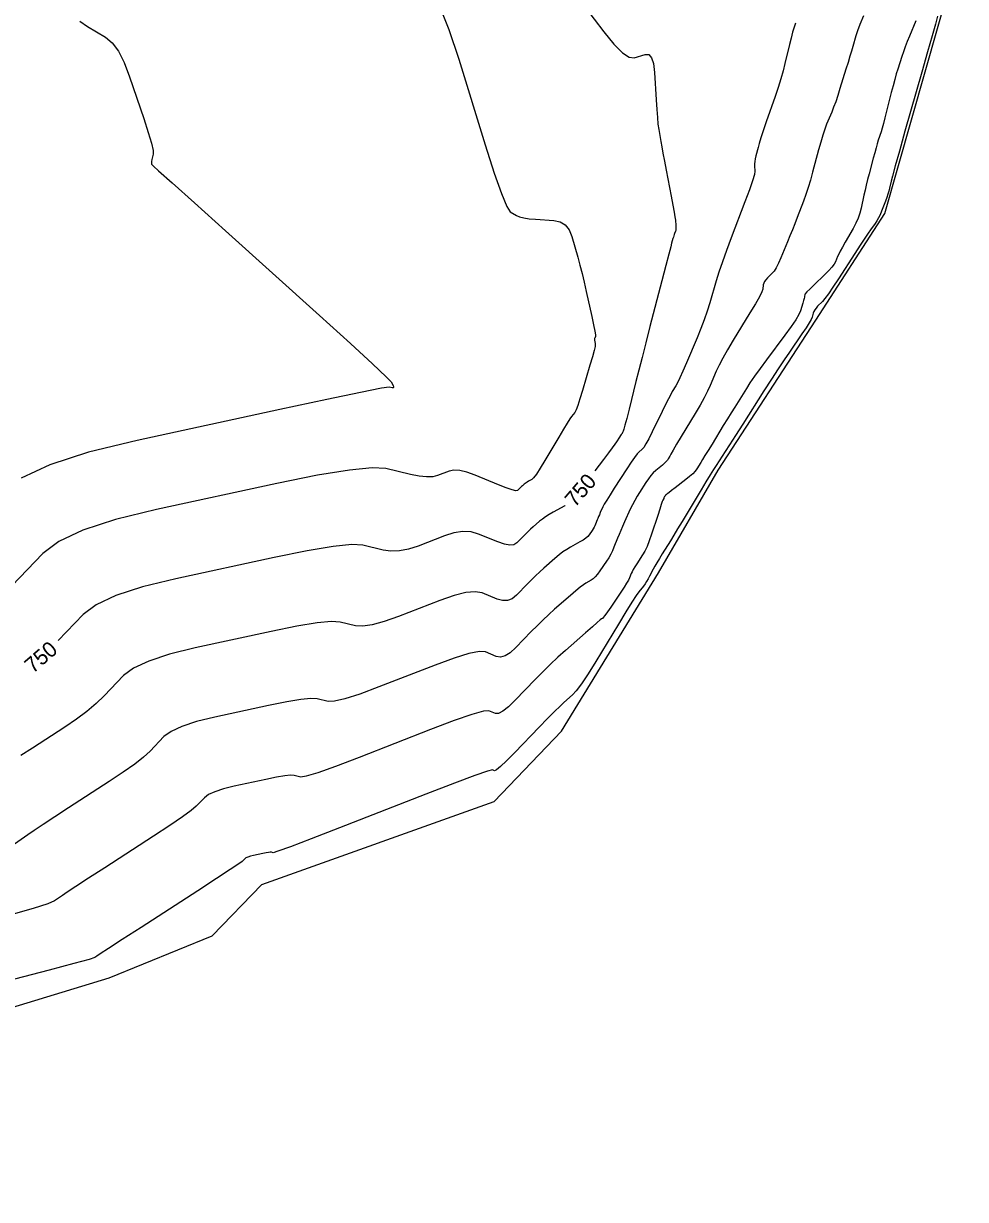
# Model space of a CAD drawing. Extents: x 2079879 to 2092887, y 778083 to 784051.
# Drawn here: x 2084480.9 to 2084652.5, y 780446.5 to 780660.6 of the extents above; entities that cross this region are included whole.
import ezdxf

# ---------------------------------------------------------------- set-up
doc = ezdxf.new("R2010")
doc.units = 0
for name, color, linetype in [('DT_X_Contour_Major', 7, 'Continuous'), ('DT_X_Contour_Minor', 7, 'Continuous'), ('DT_X_TIN_Hull', 7, 'Continuous')]:
    doc.layers.add(name, color=color, linetype=linetype)

msp = doc.modelspace()

# ---------------------------------------------------------------- linework, layer by layer
at = {"layer": 'DT_X_Contour_Major'}
for points in [[(2084581.34, 780666.04), (2084586.65, 780659.08), (2084588.48, 780656.82), (2084590.01, 780655.28), (2084591.23, 780654.45), (2084592.14, 780654.33), (2084594.15, 780654.96), (2084594.82, 780654.93), (2084595.33, 780654.38), (2084595.68, 780653.3), (2084595.87, 780651.69), (2084596.15, 780646.71), (2084596.26, 780644.97), (2084596.38, 780643.49), (2084596.5, 780642.28), (2084596.64, 780641.32), (2084597.01, 780639.12), (2084597.17, 780638.17), (2084597.39, 780636.99), (2084597.66, 780635.56), (2084597.98, 780633.9), (2084598.91, 780629.14), (2084599.21, 780627.53), (2084599.44, 780626.27), (2084599.59, 780625.37), (2084599.66, 780624.82), (2084599.74, 780623.81), (2084599.76, 780623.47), (2084599.75, 780623.17), (2084599.73, 780622.94), (2084599.68, 780622.76), (2084599.52, 780622.35), (2084599.46, 780622.17), (2084599.39, 780621.96), (2084599.31, 780621.72), (2084599.22, 780621.43), (2084598.98, 780620.61), (2084598.81, 780619.96), (2084598.45, 780618.59), (2084597.91, 780616.53), (2084597.19, 780613.76), (2084595.04, 780605.44), (2084594.27, 780602.47), (2084593.59, 780599.81), (2084592.99, 780597.45), (2084592.48, 780595.41), (2084591.22, 780590.36), (2084590.8, 780588.69), (2084590.48, 780587.47), (2084590.28, 780586.71), (2084590.18, 780586.39), (2084590.06, 780586.14), (2084590.02, 780586.06), (2084589.98, 780586), (2084589.96, 780585.96), (2084589.95, 780585.94), (2084589.93, 780585.92), (2084589.9, 780585.88), (2084589.81, 780585.75), (2084589.68, 780585.56), (2084589.5, 780585.28), (2084588.95, 780584.44), (2084588.65, 780584), (2084588.16, 780583.32), (2084587.47, 780582.4), (2084586.59, 780581.24), (2084584.99, 780579.12)], [(2084579.58, 780572.82), (2084579.52, 780572.79), (2084577.41, 780571.63), (2084576.66, 780571.2), (2084576, 780570.78), (2084575.43, 780570.37), (2084574.94, 780569.97), (2084573.75, 780568.93), (2084573.3, 780568.53), (2084572.86, 780568.12), (2084572.42, 780567.69), (2084571.98, 780567.24), (2084570.81, 780566.03), (2084570.26, 780565.7), (2084569.49, 780565.61), (2084568.51, 780565.78), (2084567.31, 780566.2), (2084563.82, 780567.64), (2084562.45, 780568.03), (2084560.95, 780568.11), (2084559.33, 780567.87), (2084557.59, 780567.33), (2084552.78, 780565.46), (2084551.03, 780564.88), (2084549.38, 780564.57), (2084547.85, 780564.51), (2084546.42, 780564.72), (2084542.75, 780565.6), (2084540.7, 780565.71), (2084537.33, 780565.37), (2084532.61, 780564.59), (2084526.57, 780563.36), (2084508.67, 780559.5), (2084502.58, 780558), (2084497.73, 780556.42), (2084494.13, 780554.75), (2084491.78, 780553), (2084487.23, 780548.25)]]:
    msp.add_lwpolyline(points, dxfattribs=at)
at = {"layer": 'DT_X_Contour_Minor'}
for points in [[(2084556.57, 780664.07), (2084558.41, 780659.5), (2084560.22, 780654.08), (2084565.04, 780638.52), (2084566.67, 780633.38), (2084567.97, 780629.63), (2084568.93, 780627.28), (2084569.54, 780626.33), (2084570.74, 780625.63), (2084571.29, 780625.39), (2084572.04, 780625.2), (2084573, 780625.06), (2084574.16, 780624.96), (2084577.52, 780624.75), (2084578.68, 780624.51), (2084579.61, 780623.94), (2084580.33, 780623.03), (2084580.83, 780621.8), (2084581.88, 780618.06), (2084582.27, 780616.62), (2084582.66, 780615.1), (2084583.04, 780613.51), (2084583.43, 780611.83), (2084584.44, 780607.24), (2084584.77, 780605.73), (2084584.99, 780604.61), (2084585.1, 780603.91), (2084585.11, 780603.6), (2084585, 780603.33), (2084584.96, 780603.22), (2084584.95, 780603.08), (2084584.95, 780602.91), (2084584.98, 780602.73), (2084585.06, 780602.19), (2084585.03, 780601.8), (2084584.86, 780601.04), (2084584.56, 780599.89), (2084584.11, 780598.36), (2084582.76, 780593.78), (2084582.29, 780592.24), (2084581.89, 780591.06), (2084581.57, 780590.24), (2084581.32, 780589.78), (2084580.75, 780589.03), (2084580.44, 780588.59), (2084579.95, 780587.81), (2084579.28, 780586.71), (2084578.42, 780585.28), (2084575.88, 780581.03), (2084575.02, 780579.62), (2084574.34, 780578.57), (2084573.84, 780577.9), (2084573.51, 780577.58), (2084572.88, 780577.24), (2084572.66, 780577.11), (2084572.46, 780576.98), (2084572.29, 780576.86), (2084572.14, 780576.74), (2084571.79, 780576.43), (2084571.65, 780576.31), (2084571.52, 780576.19), (2084571.39, 780576.06), (2084571.26, 780575.93), (2084570.91, 780575.56), (2084570.59, 780575.53), (2084569.91, 780575.69), (2084568.86, 780576.05), (2084567.45, 780576.61), (2084563.19, 780578.38), (2084561.69, 780578.92), (2084560.4, 780579.22), (2084559.31, 780579.28), (2084558.43, 780579.09), (2084556.35, 780578.29), (2084555.46, 780578.07), (2084554.34, 780578.03), (2084552.99, 780578.17), (2084551.42, 780578.49), (2084546.92, 780579.57), (2084544.41, 780579.71), (2084540.27, 780579.29), (2084534.49, 780578.33), (2084527.08, 780576.83), (2084505.13, 780572.09), (2084497.66, 780570.26), (2084491.72, 780568.32), (2084487.31, 780566.27), (2084484.43, 780564.12), (2084478.77, 780558.23)], [(2084643.5, 780661.07), (2084642.33, 780658.32), (2084641.91, 780657.32), (2084641.54, 780656.35), (2084641.21, 780655.44), (2084640.91, 780654.57), (2084640.19, 780652.31), (2084639.91, 780651.41), (2084639.62, 780650.4), (2084639.32, 780649.28), (2084639.01, 780648.06), (2084638.15, 780644.63), (2084637.84, 780643.44), (2084637.57, 780642.42), (2084637.34, 780641.57), (2084637.14, 780640.9), (2084636.64, 780639.35), (2084636.45, 780638.71), (2084636.23, 780637.94), (2084635.98, 780637.06), (2084635.71, 780636.06), (2084634.96, 780633.23), (2084634.69, 780632.19), (2084634.45, 780631.19), (2084634.22, 780630.24), (2084634.02, 780629.33), (2084633.52, 780626.96), (2084633.28, 780626.06), (2084632.96, 780625.15), (2084632.55, 780624.23), (2084632.05, 780623.29), (2084630.61, 780620.77), (2084630.12, 780619.9), (2084629.72, 780619.17), (2084629.42, 780618.59), (2084629.22, 780618.15), (2084628.82, 780617.18), (2084628.59, 780616.77), (2084628.2, 780616.26), (2084627.65, 780615.65), (2084626.94, 780614.94), (2084624.83, 780612.91), (2084624.14, 780612.24), (2084623.64, 780611.73), (2084623.34, 780611.38), (2084623.23, 780611.2), (2084623.2, 780610.94), (2084623.17, 780610.79), (2084623.11, 780610.53), (2084623.01, 780610.17), (2084622.87, 780609.7), (2084622.46, 780608.3), (2084622.17, 780607.63), (2084621.6, 780606.66), (2084620.75, 780605.41), (2084619.63, 780603.87), (2084616.26, 780599.36), (2084615.09, 780597.77), (2084614.09, 780596.37), (2084613.26, 780595.16), (2084612.6, 780594.15), (2084611.08, 780591.72), (2084610.48, 780590.76), (2084609.83, 780589.72), (2084609.14, 780588.59), (2084608.39, 780587.38), (2084606.34, 780584.03), (2084605.63, 780582.88), (2084605.05, 780581.93), (2084604.6, 780581.2), (2084604.28, 780580.67), (2084603.59, 780579.54), (2084603.27, 780579.1), (2084602.83, 780578.62), (2084602.27, 780578.11), (2084601.59, 780577.56), (2084599.6, 780576.04), (2084598.95, 780575.54), (2084598.47, 780575.17), (2084598.16, 780574.94), (2084598.04, 780574.84), (2084597.93, 780574.75), (2084597.89, 780574.71), (2084597.86, 780574.67), (2084597.82, 780574.63), (2084597.79, 780574.58), (2084597.71, 780574.46), (2084597.67, 780574.4), (2084597.63, 780574.33), (2084597.59, 780574.23), (2084597.54, 780574.12), (2084597.39, 780573.81), (2084597.29, 780573.54), (2084597.1, 780572.99), (2084596.82, 780572.14), (2084596.45, 780571.01), (2084595.33, 780567.59), (2084594.91, 780566.39), (2084594.5, 780565.37), (2084594.1, 780564.51), (2084593.7, 780563.83), (2084592.64, 780562.24), (2084592.28, 780561.68), (2084591.99, 780561.19), (2084591.77, 780560.78), (2084591.61, 780560.45), (2084591.3, 780559.66), (2084591.11, 780559.27), (2084590.79, 780558.71), (2084590.31, 780557.97), (2084589.7, 780557.05), (2084587.88, 780554.35), (2084587.28, 780553.46), (2084586.83, 780552.82), (2084586.53, 780552.42), (2084586.39, 780552.26), (2084586.22, 780552.17), (2084585.99, 780551.99), (2084585.43, 780551.51), (2084584.54, 780550.74), (2084583.32, 780549.67), (2084579.63, 780546.43), (2084578.25, 780545.19), (2084576.87, 780543.9), (2084575.5, 780542.57), (2084574.14, 780541.18), (2084570.5, 780537.41), (2084569.25, 780536.2), (2084568.23, 780535.39), (2084567.44, 780534.97), (2084566.89, 780534.96), (2084565.7, 780535.45), (2084564.7, 780535.37), (2084562.6, 780534.78), (2084559.38, 780533.66), (2084555.06, 780532.02), (2084542.05, 780526.97), (2084537.73, 780525.32), (2084534.51, 780524.18), (2084532.4, 780523.53), (2084531.41, 780523.39), (2084530.23, 780523.67), (2084529.57, 780523.71), (2084528.49, 780523.6), (2084526.97, 780523.35), (2084525.03, 780522.96), (2084519.27, 780521.71), (2084517.32, 780521.23), (2084515.76, 780520.72), (2084514.6, 780520.19), (2084513.85, 780519.62), (2084512.37, 780518.08), (2084511.46, 780517.3), (2084509.87, 780516.14), (2084507.58, 780514.57), (2084504.59, 780512.62), (2084495.71, 780506.88), (2084492.73, 780504.95), (2084490.45, 780503.47), (2084488.87, 780502.43), (2084487.99, 780501.83), (2084486.56, 780500.84), (2084485.32, 780500.31), (2084482.66, 780499.47), (2084478.58, 780498.32)], [(2084633.94, 780661.97), (2084633.29, 780660.45), (2084632.83, 780659.24), (2084632.53, 780658.35), (2084631.98, 780656.39), (2084631.75, 780655.58), (2084631.47, 780654.63), (2084631.14, 780653.53), (2084630.75, 780652.28), (2084629.65, 780648.76), (2084629.25, 780647.5), (2084628.87, 780646.37), (2084628.5, 780645.36), (2084628.15, 780644.47), (2084627.23, 780642.27), (2084626.88, 780641.36), (2084626.52, 780640.28), (2084626.14, 780639.02), (2084625.74, 780637.59), (2084624.67, 780633.56), (2084624.27, 780632.09), (2084623.85, 780630.72), (2084623.43, 780629.45), (2084623.01, 780628.27), (2084621.85, 780625.27), (2084621.42, 780624.14), (2084620.98, 780623.03), (2084620.54, 780621.93), (2084620.09, 780620.83), (2084618.88, 780617.93), (2084618.44, 780616.94), (2084618.04, 780616.14), (2084617.66, 780615.53), (2084617.31, 780615.12), (2084616.43, 780614.27), (2084616.13, 780613.95), (2084615.91, 780613.64), (2084615.77, 780613.33), (2084615.69, 780613.02), (2084615.6, 780612.22), (2084615.43, 780611.72), (2084614.98, 780610.83), (2084614.25, 780609.56), (2084613.25, 780607.89), (2084610.22, 780602.93), (2084609.17, 780601.19), (2084608.31, 780599.66), (2084607.62, 780598.36), (2084607.12, 780597.27), (2084606.02, 780594.69), (2084605.54, 780593.64), (2084604.92, 780592.44), (2084604.17, 780591.09), (2084603.28, 780589.59), (2084600.73, 780585.38), (2084599.88, 780583.98), (2084599.25, 780582.92), (2084598.83, 780582.21), (2084598.63, 780581.84), (2084598.38, 780581.33), (2084598.24, 780581.12), (2084598.01, 780580.85), (2084597.7, 780580.55), (2084597.3, 780580.19), (2084596.1, 780579.18), (2084595.65, 780578.76), (2084595.21, 780578.27), (2084594.76, 780577.7), (2084594.31, 780577.05), (2084593.12, 780575.22), (2084592.68, 780574.52), (2084592.26, 780573.77), (2084591.85, 780572.98), (2084591.45, 780572.14), (2084590.41, 780569.86), (2084590.04, 780569.03), (2084589.7, 780568.26), (2084589.4, 780567.55), (2084589.14, 780566.9), (2084588.48, 780565.22), (2084588.2, 780564.59), (2084587.88, 780563.96), (2084587.52, 780563.31), (2084587.1, 780562.67), (2084585.92, 780560.93), (2084585.49, 780560.33), (2084585.08, 780559.85), (2084584.7, 780559.48), (2084584.33, 780559.23), (2084583.38, 780558.71), (2084582.94, 780558.42), (2084582.31, 780557.95), (2084581.51, 780557.29), (2084580.53, 780556.44), (2084577.67, 780553.93), (2084576.6, 780552.97), (2084575.53, 780551.98), (2084574.47, 780550.94), (2084573.42, 780549.87), (2084570.6, 780546.95), (2084569.59, 780546.03), (2084568.65, 780545.46), (2084567.8, 780545.24), (2084567.03, 780545.37), (2084565.07, 780546.18), (2084563.95, 780546.26), (2084562.05, 780545.89), (2084559.36, 780545.06), (2084555.9, 780543.79), (2084545.63, 780539.8), (2084542.16, 780538.51), (2084539.47, 780537.64), (2084537.55, 780537.19), (2084536.41, 780537.17), (2084534.4, 780537.65), (2084533.28, 780537.71), (2084531.43, 780537.52), (2084528.85, 780537.1), (2084525.54, 780536.42), (2084515.74, 780534.31), (2084512.4, 780533.49), (2084509.75, 780532.62), (2084507.78, 780531.71), (2084506.49, 780530.75), (2084503.97, 780528.12), (2084502.79, 780527.03), (2084501.16, 780525.74), (2084499.07, 780524.25), (2084496.52, 780522.56), (2084489.12, 780517.77), (2084486.58, 780516.12), (2084484.49, 780514.76), (2084482.87, 780513.68), (2084481.71, 780512.89), (2084479.24, 780511.17)], [(2084647.41, 780661.91), (2084647.03, 780660.51), (2084646.43, 780658.34), (2084645.61, 780655.43), (2084644.57, 780651.76), (2084641.5, 780640.97), (2084640.48, 780637.37), (2084639.72, 780634.66), (2084639.22, 780632.83), (2084638.98, 780631.9), (2084638.69, 780630.59), (2084638.57, 780630.08), (2084638.4, 780629.52), (2084638.19, 780628.91), (2084637.94, 780628.25), (2084637.23, 780626.44), (2084636.95, 780625.79), (2084636.67, 780625.2), (2084636.37, 780624.67), (2084636.05, 780624.2), (2084635.2, 780623.03), (2084634.79, 780622.43), (2084634.17, 780621.51), (2084633.35, 780620.27), (2084632.34, 780618.71), (2084629.38, 780614.12), (2084628.36, 780612.57), (2084627.54, 780611.37), (2084626.92, 780610.52), (2084626.49, 780610.01), (2084625.59, 780609.12), (2084625.29, 780608.79), (2084625.05, 780608.47), (2084624.88, 780608.17), (2084624.77, 780607.88), (2084624.57, 780607.12), (2084624.4, 780606.72), (2084624.03, 780606.07), (2084623.47, 780605.19), (2084622.71, 780604.07), (2084620.43, 780600.76), (2084619.5, 780599.38), (2084618.42, 780597.75), (2084617.19, 780595.86), (2084615.81, 780593.72), (2084611.93, 780587.64), (2084610.6, 780585.57), (2084609.53, 780583.91), (2084608.73, 780582.66), (2084608.19, 780581.82), (2084607.09, 780580.14), (2084606.61, 780579.39), (2084605.99, 780578.4), (2084605.24, 780577.16), (2084604.34, 780575.68), (2084601.79, 780571.42), (2084600.88, 780569.91), (2084600.07, 780568.57), (2084599.36, 780567.41), (2084598.76, 780566.42), (2084597.27, 780564.01), (2084596.76, 780563.16), (2084596.31, 780562.41), (2084595.94, 780561.77), (2084595.65, 780561.23), (2084594.97, 780559.94), (2084594.71, 780559.46), (2084594.43, 780559.01), (2084594.14, 780558.58), (2084593.83, 780558.17), (2084592.99, 780557.11), (2084592.52, 780556.44), (2084591.75, 780555.24), (2084590.67, 780553.5), (2084589.28, 780551.23), (2084585.17, 780544.45), (2084583.75, 780542.16), (2084582.57, 780540.38), (2084581.62, 780539.11), (2084580.92, 780538.34), (2084579.36, 780536.98), (2084578.65, 780536.31), (2084577.65, 780535.35), (2084576.39, 780534.07), (2084574.86, 780532.49), (2084570.4, 780527.88), (2084568.92, 780526.37), (2084567.81, 780525.31), (2084567.09, 780524.7), (2084566.74, 780524.54), (2084566.33, 780524.71), (2084565.46, 780524.48), (2084563.15, 780523.66), (2084559.4, 780522.26), (2084554.21, 780520.26), (2084538.47, 780514.14), (2084533.29, 780512.14), (2084529.55, 780510.71), (2084527.26, 780509.87), (2084526.41, 780509.62), (2084526.06, 780509.7), (2084525.86, 780509.71), (2084525.54, 780509.68), (2084525.09, 780509.6), (2084524.52, 780509.49), (2084522.81, 780509.12), (2084522.23, 780508.98), (2084521.77, 780508.83), (2084521.43, 780508.67), (2084521.2, 780508.5), (2084520.76, 780508.04), (2084520.13, 780507.58), (2084518.57, 780506.53), (2084516.09, 780504.9), (2084512.67, 780502.68), (2084502.31, 780495.99), (2084498.89, 780493.78), (2084496.41, 780492.17), (2084494.87, 780491.17), (2084494.26, 780490.77), (2084493.89, 780490.51), (2084492.87, 780490.19), (2084490.09, 780489.42), (2084485.55, 780488.21), (2084479.25, 780486.56)], [(2084621.55, 780660.67), (2084621.3, 780659.92), (2084621.03, 780659.02), (2084620.75, 780657.96), (2084620.45, 780656.75), (2084619.63, 780653.32), (2084619.29, 780651.98), (2084618.88, 780650.53), (2084618.39, 780648.96), (2084617.82, 780647.29), (2084616.23, 780642.67), (2084615.68, 780641.08), (2084615.25, 780639.78), (2084614.94, 780638.77), (2084614.73, 780638.05), (2084614.34, 780636.52), (2084614.21, 780635.97), (2084614.13, 780635.48), (2084614.09, 780635.04), (2084614.1, 780634.66), (2084614.17, 780633.72), (2084614.08, 780633.11), (2084613.74, 780631.97), (2084613.17, 780630.31), (2084612.35, 780628.12), (2084609.85, 780621.6), (2084608.98, 780619.28), (2084608.23, 780617.19), (2084607.6, 780615.34), (2084607.1, 780613.73), (2084605.93, 780609.75), (2084605.46, 780608.23), (2084604.91, 780606.66), (2084604.3, 780605.04), (2084603.61, 780603.36), (2084601.69, 780598.83), (2084601.02, 780597.29), (2084600.48, 780596.08), (2084600.06, 780595.2), (2084599.76, 780594.63), (2084599.11, 780593.57), (2084598.82, 780593.05), (2084598.41, 780592.27), (2084597.89, 780591.25), (2084597.26, 780589.98), (2084595.44, 780586.25), (2084594.82, 780585), (2084594.31, 780584.05), (2084593.91, 780583.41), (2084593.62, 780583.07), (2084593.02, 780582.55), (2084592.71, 780582.22), (2084592.24, 780581.6), (2084591.62, 780580.7), (2084590.84, 780579.52), (2084588.54, 780575.99), (2084587.76, 780574.78), (2084587.16, 780573.81), (2084586.72, 780573.07), (2084586.46, 780572.57), (2084585.99, 780571.54), (2084585.82, 780571.16), (2084585.67, 780570.82), (2084585.54, 780570.49), (2084585.42, 780570.2), (2084585.12, 780569.44), (2084584.99, 780569.16), (2084584.85, 780568.87), (2084584.68, 780568.58), (2084584.5, 780568.29), (2084583.96, 780567.5), (2084583.71, 780567.2), (2084583.34, 780566.88), (2084582.86, 780566.55), (2084582.27, 780566.2), (2084580.54, 780565.25), (2084579.88, 780564.85), (2084579.19, 780564.38), (2084578.48, 780563.83), (2084577.73, 780563.21), (2084575.71, 780561.43), (2084574.95, 780560.75), (2084574.2, 780560.05), (2084573.44, 780559.31), (2084572.7, 780558.55), (2084570.7, 780556.49), (2084569.92, 780555.86), (2084569.07, 780555.54), (2084568.15, 780555.51), (2084567.17, 780555.79), (2084564.44, 780556.91), (2084563.2, 780557.14), (2084561.5, 780557), (2084559.35, 780556.47), (2084556.75, 780555.56), (2084549.2, 780552.63), (2084546.59, 780551.7), (2084544.43, 780551.11), (2084542.7, 780550.85), (2084541.41, 780550.94), (2084538.57, 780551.62), (2084536.99, 780551.71), (2084534.38, 780551.45), (2084530.73, 780550.84), (2084526.05, 780549.89), (2084512.2, 780546.9), (2084507.49, 780545.75), (2084503.74, 780544.52), (2084500.96, 780543.23), (2084499.14, 780541.87), (2084495.57, 780538.16), (2084494.12, 780536.76), (2084492.45, 780535.35), (2084490.56, 780533.93), (2084488.45, 780532.5), (2084482.53, 780528.67), (2084480.42, 780527.3)], [(2084491.16, 780661.01), (2084492.55, 780660.07), (2084495.85, 780658.11), (2084497.05, 780657.11), (2084498.18, 780655.58), (2084499.25, 780653.51), (2084500.24, 780650.92), (2084502.81, 780643.28), (2084503.64, 780640.73), (2084504.2, 780638.8), (2084504.51, 780637.5), (2084504.54, 780636.81), (2084504.29, 780635.82), (2084504.22, 780635.48), (2084504.2, 780635.21), (2084504.24, 780635.01), (2084504.32, 780634.88), (2084504.61, 780634.61), (2084505.51, 780633.8), (2084507.98, 780631.57), (2084512.04, 780627.92), (2084517.68, 780622.84), (2084534.81, 780607.41), (2084540.45, 780602.32), (2084544.51, 780598.61), (2084547, 780596.28), (2084547.91, 780595.34), (2084548.24, 780594.68), (2084548.32, 780594.46), (2084548.32, 780594.33), (2084548.23, 780594.26), (2084548.07, 780594.28), (2084547.51, 780594.41), (2084546.11, 780594.19), (2084542.32, 780593.43), (2084536.15, 780592.13), (2084527.59, 780590.3), (2084501.59, 780584.69), (2084492.75, 780582.52), (2084485.71, 780580.22), (2084480.49, 780577.8)]]:
    msp.add_lwpolyline(points, dxfattribs=at)
at = {"layer": 'DT_X_TIN_Hull'}
msp.add_lwpolyline([(2084221.09, 780468.71), (2084252.85, 780468.7), (2084255.71, 780449.52), (2084265.08, 780446.47), (2084292.12, 780448.11), (2084342.85, 780458.7), (2084395.13, 780467.65), (2084446.62, 780471.64), (2084496.49, 780486.83), (2084515.26, 780494.46), (2084524.3, 780503.82), (2084566.67, 780518.93), (2084578.9, 780531.73), (2084596.61, 780560.59), (2084607.47, 780579.25), (2084625.27, 780606.56), (2084637.81, 780626.01), (2084652.52, 780677.63)], dxfattribs=at)

# ---------------------------------------------------------------- texts
at = {"layer": 'DT_X_Contour_Major'}
for rotation, p in [(49.3553, (2084581.39, 780572.36)), (40.7257, (2084482.61, 780542.15))]:
    msp.add_text('750', height=2.8, rotation=rotation, dxfattribs=at).set_placement(p)

doc.saveas('drawing.dxf')
